(* Logix 5000 project; controller L32E_PLC vendor 1 type 14 code 77 rev 20.13; software revision 20.00 *)

TASK MainTask (continuous, watchdog 500 ms) : MainProgram

MODULES
   Controller : vendor 1 type 14 code 77 (CompactLogixL32EController 0, rev 20.13)
      LocalENB : 1769-L32E Ethernet Port (CompactLogixL32Ethernet 1, rev 20.11)
         CM1T_CMLDrive : ETHERNET-MODULE (Ethernet 192.168.1.50, rev 1.1, Output RPI 10 ms)
      Local : CompactBus (CompactVirtualAdapter 3, rev 20.11)
END_MODULES

TYPE CM1T_CMLAxis :   // CML Axis
STRUCT
   Input : SINT[60];   // Data coming from the CM1-T
   Output : SINT[44];   // Data going to the CM1-T
   us50Counter : DINT;   // Controller 50us counter
   DriveStatus : CM1T_CMLDriveStatus;   // Shows status of the drive
   PositionActual : DINT;   // Actual position of the drive
   TargetActual : DINT;   // 1ms position target
   PositionError : DINT;   // Error between the current drive position and the instantaneous target position
   SpeedActual : DINT;   // Actual speed of the drive
   CurrentActual : INT;   // 0.1% of rated current
   OverloadActual : INT;   // 0.1% of overload torque
   DCVoltage : INT;   // DC voltage bus. 0.1V unit
   AnalogIN : INT;   // Value of 10bit analog input
   DigitalIN : SINT;   // Read the digital inputs
   DigitalOUT : SINT;   // Set the digital outputs
   Temperature : SINT;   // Temperature of the drive
   ErrorCode : SINT;   // Indicates error in Ethernet/IP module
   WriteValue : DINT[5];   // Write value array
   ReadValue : DINT[5];   // Read Value array
   WriteAddr : INT[5];   // Write Address array
   ReadAddr : INT[5];   // Read Address array
   ReadValueAddr : INT[5];   // Address of ReadValue
END_STRUCT
END_TYPE

TYPE CM1T_CMLDriveStatus :
STRUCT
   StatusValue : SINT;   // Indicates status and error type
   StatusValue1 : SINT;   // Additional status values
   In_Position : BOOL;   // Drive is in position and ready to move
   Moving : BOOL;   // Drive is currently moving
   Disabled : BOOL;   // Drive is disabled
   Error : BOOL;   // Drive is in an error state
   HomeAchieved : BOOL;   // Home achieved
END_STRUCT
END_TYPE

ADD_ON_INSTRUCTION CM1T_CMLDataExchange   (* revision 1.2, vendor Myostat Motion Control *)
// CM1T CML Data Exchange
VAR_IN_OUT
   DriveInput : AB:ETHERNET_MODULE_SINT_60Bytes:I:0; {required}
   DriveOutput : AB:ETHERNET_MODULE_SINT_44Bytes:O:0; {required}
        .DATA[0]   // Copy outputs to drive
   CM1T_CMLAxis : CM1T_CMLAxis; {required}
        .OUTPUT[28]   // Write Addr5
        .OUTPUT[20]   // Write Addr1
        .OUTPUT[14]   // Controlword
        .DRIVESTATUS.MOVING   // Moving
        .CURRENTACTUAL   // Current
        .OUTPUT[17]   // WriteData
        .DRIVESTATUS.STATUSVALUE   // Status
        .DRIVESTATUS.ERROR   // Error
        .DIGITALIN   // DigitalIN
        .POSITIONERROR   // Position Error
        .OUTPUT[0]   // Write Value1
        .OUTPUT[18]   // WriteAddress
        .DCVOLTAGE   // DC Voltage
        .OUTPUT[30]   // Read Addr1
        .OUTPUT[8]   // Write Value3
        .OUTPUT[16]   // Write Value5
        .OUTPUT[32]   // Read Addr2
        .OUTPUT[21]   // Digital OUT
        .OUTPUT[24]   // Write Addr3
        .INPUT   // Copy input from drive
        .POSITIONACTUAL   // Position
        .TEMPERATURE   // Temperature
        .ANALOGIN   // AnalogIN
        .OVERLOADACTUAL   // Torque
        .OUTPUT[10]   // AccelerationTarget
        .OUTPUT[12]   // Write Value4
        .ERRORCODE   // ErrorCode
        .SPEEDACTUAL   // Speed
        .OUTPUT[38]   // Read Addr5
        .OUTPUT[26]   // Write Addr4
        .OUTPUT[22]   // Write Addr2
        .OUTPUT[34]   // Read Addr3
        .OUTPUT[36]   // Read Addr4
        .OUTPUT[4]   // Write Value2
        .CONTROLWORD.START   // Controlword.Start Off
        .DRIVESTATUS.IN_POSITION   // In Position
        .MODEOFOPERATIONDISPLAY   // Mode Display
END_VAR

ROUTINE Logic   (* ladder *)
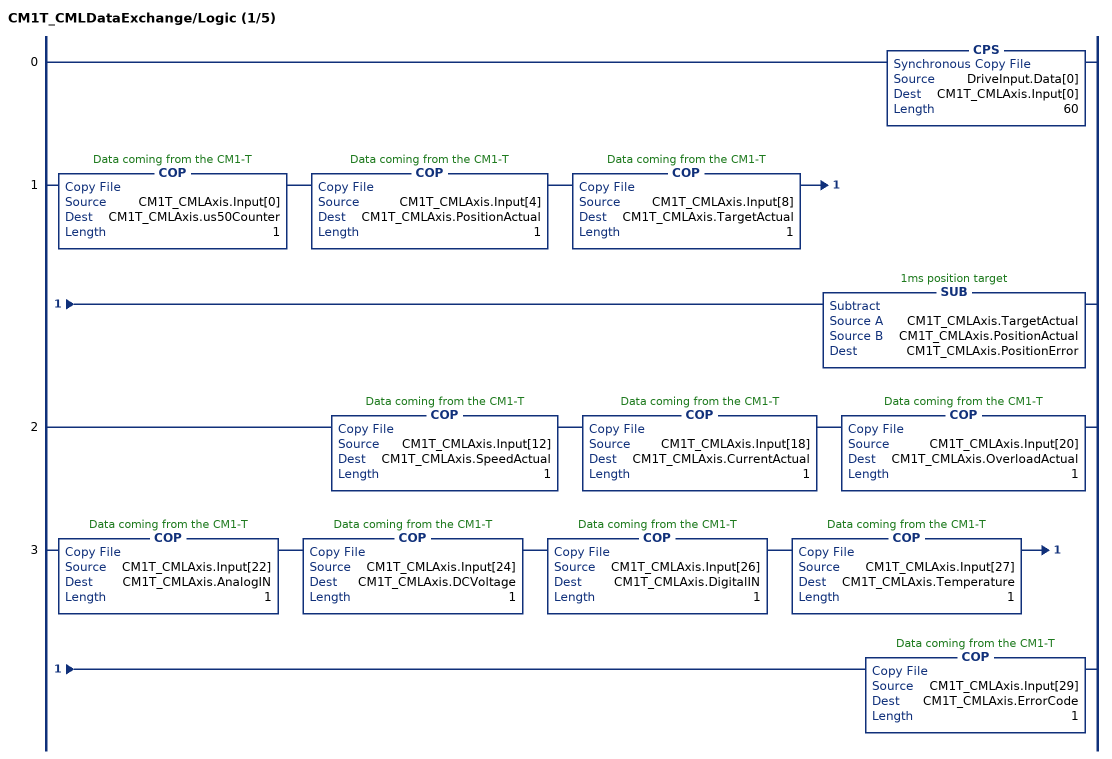
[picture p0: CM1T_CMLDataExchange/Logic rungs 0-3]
   0: CPS(DriveInput.Data[0],CM1T_CMLAxis.Input[0],60);
   1: COP(CM1T_CMLAxis.Input[0],CM1T_CMLAxis.us50Counter,1)COP(CM1T_CMLAxis.Input[4],CM1T_CMLAxis.PositionActual,1)COP(CM1T_CMLAxis.Input[8],CM1T_CMLAxis.TargetActual,1)SUB(CM1T_CMLAxis.TargetActual,CM1T_CMLAxis.PositionActual,CM1T_CMLAxis.PositionError);
   2: COP(CM1T_CMLAxis.Input[12],CM1T_CMLAxis.SpeedActual,1)COP(CM1T_CMLAxis.Input[18],CM1T_CMLAxis.CurrentActual,1)COP(CM1T_CMLAxis.Input[20],CM1T_CMLAxis.OverloadActual,1);
   3: COP(CM1T_CMLAxis.Input[22],CM1T_CMLAxis.AnalogIN,1)COP(CM1T_CMLAxis.Input[24],CM1T_CMLAxis.DCVoltage,1)COP(CM1T_CMLAxis.Input[26],CM1T_CMLAxis.DigitalIN,1)COP(CM1T_CMLAxis.Input[27],CM1T_CMLAxis.Temperature,1)COP(CM1T_CMLAxis.Input[29],CM1T_CMLAxis.ErrorCode,1);
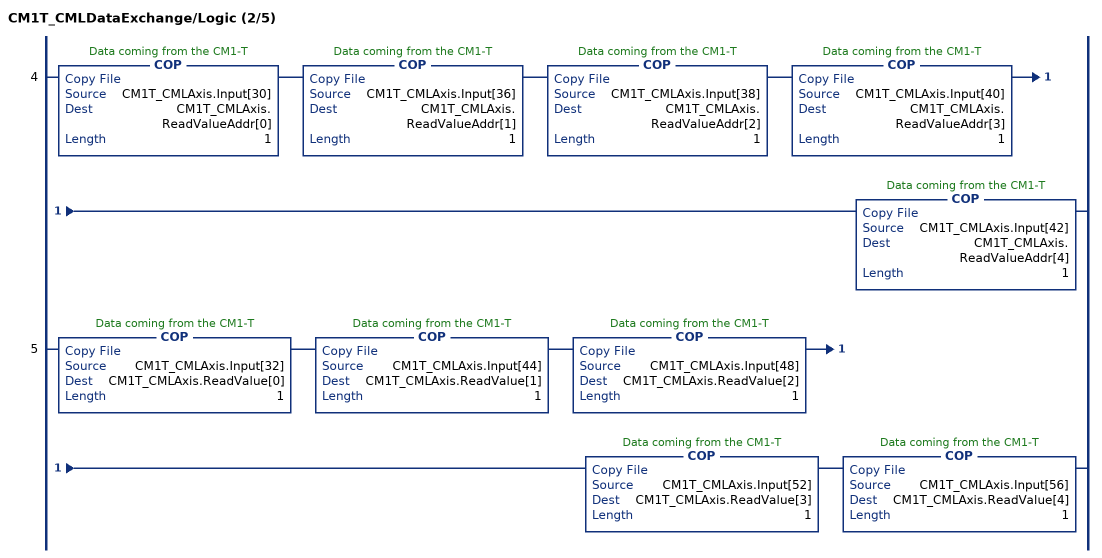
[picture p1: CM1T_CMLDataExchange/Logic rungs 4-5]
   4: COP(CM1T_CMLAxis.Input[30],CM1T_CMLAxis.ReadValueAddr[0],1)COP(CM1T_CMLAxis.Input[36],CM1T_CMLAxis.ReadValueAddr[1],1)COP(CM1T_CMLAxis.Input[38],CM1T_CMLAxis.ReadValueAddr[2],1)COP(CM1T_CMLAxis.Input[40],CM1T_CMLAxis.ReadValueAddr[3],1)COP(CM1T_CMLAxis.Input[42],CM1T_CMLAxis.ReadValueAddr[4],1);
   5: COP(CM1T_CMLAxis.Input[32],CM1T_CMLAxis.ReadValue[0],1)COP(CM1T_CMLAxis.Input[44],CM1T_CMLAxis.ReadValue[1],1)COP(CM1T_CMLAxis.Input[48],CM1T_CMLAxis.ReadValue[2],1)COP(CM1T_CMLAxis.Input[52],CM1T_CMLAxis.ReadValue[3],1)COP(CM1T_CMLAxis.Input[56],CM1T_CMLAxis.ReadValue[4],1);
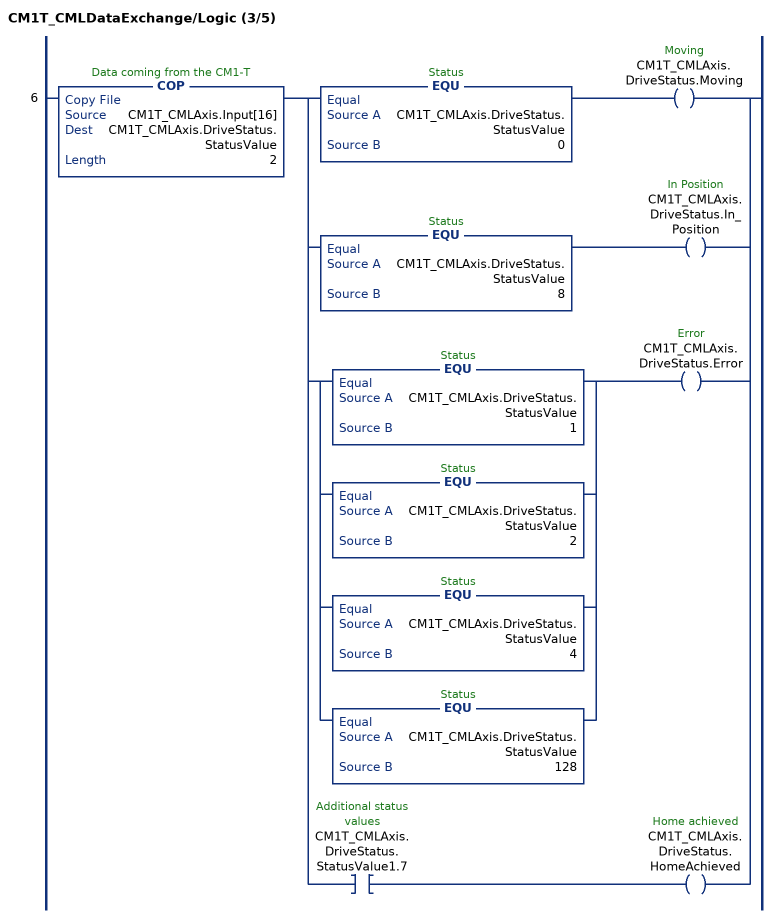
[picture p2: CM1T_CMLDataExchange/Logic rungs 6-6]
   6: COP(CM1T_CMLAxis.Input[16],CM1T_CMLAxis.DriveStatus.StatusValue,2)[EQU(CM1T_CMLAxis.DriveStatus.StatusValue,0) OTE(CM1T_CMLAxis.DriveStatus.Moving) ,EQU(CM1T_CMLAxis.DriveStatus.StatusValue,8) OTE(CM1T_CMLAxis.DriveStatus.In_Position) ,[EQU(CM1T_CMLAxis.DriveStatus.StatusValue,1) ,EQU(CM1T_CMLAxis.DriveStatus.StatusValue,2) ,EQU(CM1T_CMLAxis.DriveStatus.StatusValue,4) ,EQU(CM1T_CMLAxis.DriveStatus.StatusValue,128) ] OTE(CM1T_CMLAxis.DriveStatus.Error) ,XIC(CM1T_CMLAxis.DriveStatus.StatusValue1.7) OTE(CM1T_CMLAxis.DriveStatus.HomeAchieved) ];
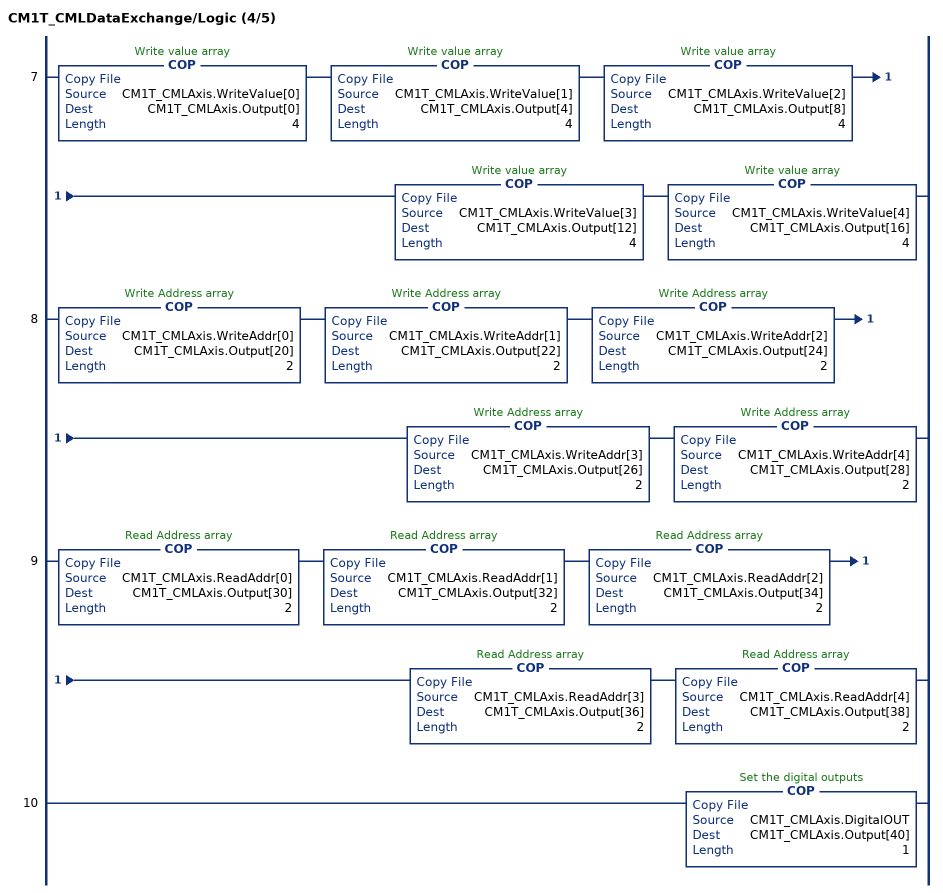
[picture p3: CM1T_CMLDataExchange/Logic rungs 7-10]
   7: COP(CM1T_CMLAxis.WriteValue[0],CM1T_CMLAxis.Output[0],4)COP(CM1T_CMLAxis.WriteValue[1],CM1T_CMLAxis.Output[4],4)COP(CM1T_CMLAxis.WriteValue[2],CM1T_CMLAxis.Output[8],4)COP(CM1T_CMLAxis.WriteValue[3],CM1T_CMLAxis.Output[12],4)COP(CM1T_CMLAxis.WriteValue[4],CM1T_CMLAxis.Output[16],4);
   8: COP(CM1T_CMLAxis.WriteAddr[0],CM1T_CMLAxis.Output[20],2)COP(CM1T_CMLAxis.WriteAddr[1],CM1T_CMLAxis.Output[22],2)COP(CM1T_CMLAxis.WriteAddr[2],CM1T_CMLAxis.Output[24],2)COP(CM1T_CMLAxis.WriteAddr[3],CM1T_CMLAxis.Output[26],2)COP(CM1T_CMLAxis.WriteAddr[4],CM1T_CMLAxis.Output[28],2);
   9: COP(CM1T_CMLAxis.ReadAddr[0],CM1T_CMLAxis.Output[30],2)COP(CM1T_CMLAxis.ReadAddr[1],CM1T_CMLAxis.Output[32],2)COP(CM1T_CMLAxis.ReadAddr[2],CM1T_CMLAxis.Output[34],2)COP(CM1T_CMLAxis.ReadAddr[3],CM1T_CMLAxis.Output[36],2)COP(CM1T_CMLAxis.ReadAddr[4],CM1T_CMLAxis.Output[38],2);
   10: COP(CM1T_CMLAxis.DigitalOUT,CM1T_CMLAxis.Output[40],1);
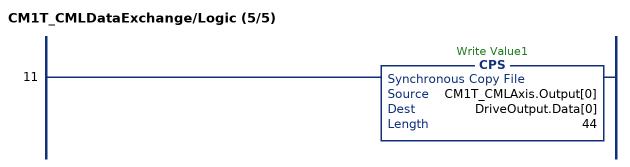
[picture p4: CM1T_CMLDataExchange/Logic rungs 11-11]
   11: CPS(CM1T_CMLAxis.Output[0],DriveOutput.Data[0],44);
END_ROUTINE
END_ADD_ON_INSTRUCTION

ADD_ON_INSTRUCTION CM1T_CMLReadRegister   (* revision 1.0 *)
// Read Register
VAR_IN_OUT
   CM1T_CMLAxis : CM1T_CMLAxis; {required}
END_VAR
VAR_INPUT
   Slot : SINT; {required}
   Address : INT; {required}
END_VAR
VAR_OUTPUT
   Value : DINT; {access Read Only, required}
   Done : BOOL; {access Read Only, visible}
END_VAR

ROUTINE Logic   (* ladder *)
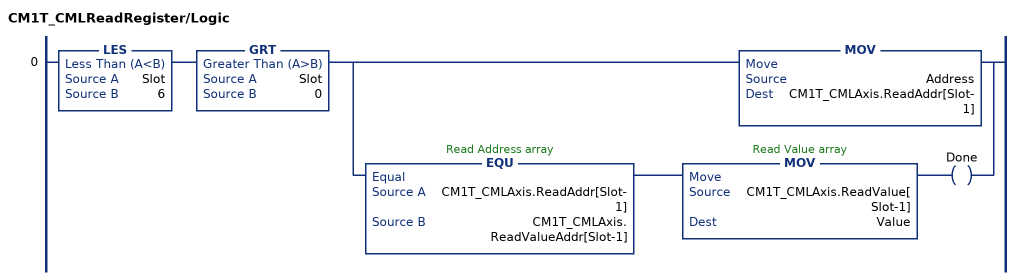
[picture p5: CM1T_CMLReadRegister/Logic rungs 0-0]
   0: LES(Slot,6)GRT(Slot,0)[MOV(Address,CM1T_CMLAxis.ReadAddr[Slot-1]) ,EQU(CM1T_CMLAxis.ReadAddr[Slot-1],CM1T_CMLAxis.ReadValueAddr[Slot-1]) MOV(CM1T_CMLAxis.ReadValue[Slot-1],Value) OTE(Done) ];
END_ROUTINE
END_ADD_ON_INSTRUCTION

ADD_ON_INSTRUCTION CM1T_CMLWriteRegister   (* revision 1.0 *)
// WriteRegister
VAR_IN_OUT
   CM1T_CMLAxis : CM1T_CMLAxis; {required}
END_VAR
VAR_INPUT
   Slot : SINT; {required}
   Address : INT; {required}
   Value : DINT; {access Read Only, required}
END_VAR
VAR_OUTPUT
   Done : BOOL; {access Read Only, visible}
END_VAR
VAR
   usCount : DINT; {access None}
END_VAR

ROUTINE Logic   (* ladder *)
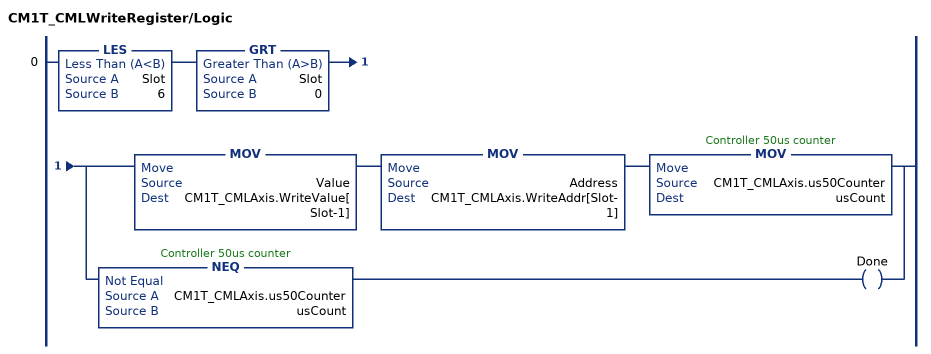
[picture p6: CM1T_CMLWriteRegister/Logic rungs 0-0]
   0: LES(Slot,6)GRT(Slot,0)[MOV(Value,CM1T_CMLAxis.WriteValue[Slot-1]) MOV(Address,CM1T_CMLAxis.WriteAddr[Slot-1]) MOV(CM1T_CMLAxis.us50Counter,usCount) ,NEQ(CM1T_CMLAxis.us50Counter,usCount) OTE(Done) ];
END_ROUTINE
END_ADD_ON_INSTRUCTION

VAR_GLOBAL   (* controller tags *)
   MSG_Control : MESSAGE;
        MessageParameters(ServiceCode := 16#000e, DestinationTag := MSG_Response, ...)
   MSG_Response : INT;
   Query : BOOL;
END_VAR

PROGRAM MainProgram   (* main routine MainRoutine *)
VAR
   CM1T_CMLDrive : CM1T_CMLAxis;
   Counter : DINT;
   FB_CM1T_CMLDataExchange : CM1T_CMLDataExchange;
   FB_CM1T_CMLReadRegister : CM1T_CMLReadRegister;
   FB_CM1T_CMLWriteRegister : CM1T_CMLWriteRegister;   // Write Register
   Run : BOOL;
   RunValue : DINT;
END_VAR

ROUTINE MainRoutine   (* ladder *)
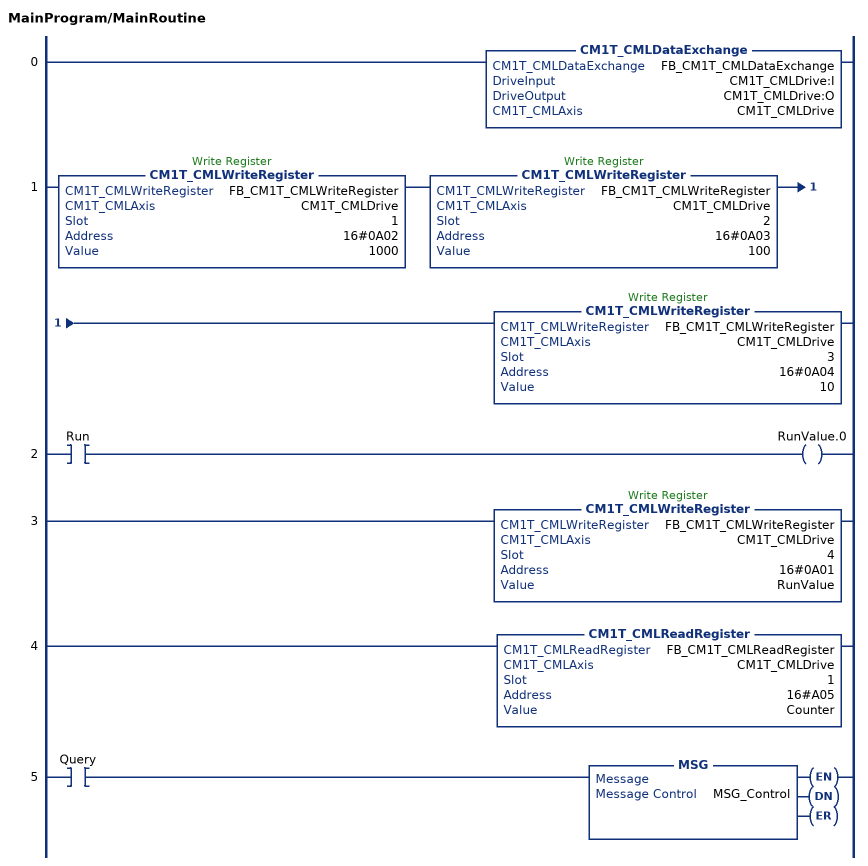
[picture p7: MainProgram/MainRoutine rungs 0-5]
   0: CM1T_CMLDataExchange(FB_CM1T_CMLDataExchange,CM1T_CMLDrive:I,CM1T_CMLDrive:O,CM1T_CMLDrive);
   1: CM1T_CMLWriteRegister(FB_CM1T_CMLWriteRegister,CM1T_CMLDrive,1,16#0A02,1000)CM1T_CMLWriteRegister(FB_CM1T_CMLWriteRegister,CM1T_CMLDrive,2,16#0A03,100)CM1T_CMLWriteRegister(FB_CM1T_CMLWriteRegister,CM1T_CMLDrive,3,16#0A04,10);
   2: XIC(Run)OTE(RunValue.0);
   3: CM1T_CMLWriteRegister(FB_CM1T_CMLWriteRegister,CM1T_CMLDrive,4,16#0A01,RunValue);
   4: CM1T_CMLReadRegister(FB_CM1T_CMLReadRegister,CM1T_CMLDrive,1,16#A05,Counter);
   5: XIC(Query)MSG(MSG_Control);
END_ROUTINE
END_PROGRAM
